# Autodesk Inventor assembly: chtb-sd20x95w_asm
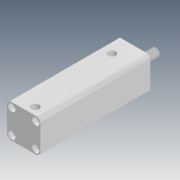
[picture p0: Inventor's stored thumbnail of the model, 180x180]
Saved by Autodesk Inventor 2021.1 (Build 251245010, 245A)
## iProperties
Company: Microsoft
Created: 2018-05
Part Number: chtb-sd20x95w_asm
Description: STEP AP214
Document SubType Name: Assembly
Designer: user
Title: chtb-sd20x95w_asm.STEP
Author: Windows
Revision Number: ÈÎºÎ
Sending System: SolidWorks 2015
Preprocessor: SwSTEP 2.0
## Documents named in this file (4)
- D:\Vault_2016\Projekty\Clamptek\Hydraulic\CHTB\CHTB-20\Inventor\CHTB-SD20x95W\chtb-sd20x95w_asm.iam
- D:\Vault_2016\Projekty\Clamptek\Hydraulic\CHTB\CHTB-20\Inventor\CHTB-SD20x95W\CHTB-SD20X95NBT.ipt
- D:\Vault_2016\Projekty\Clamptek\Hydraulic\CHTB\CHTB-20\Inventor\CHTB-SD20x95W\CHTB-SD20X95WHSG.ipt
- D:\Vault_2016\Projekty\Clamptek\Hydraulic\CHTB\CHTB-20\Inventor\CHTB-SD20x95W\QG.ipt
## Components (3 placed, 3 different names)
1. CHTB-SD20X95NBT_1
2. CHTB-SD20X95WHSG_2
3. QG_3
